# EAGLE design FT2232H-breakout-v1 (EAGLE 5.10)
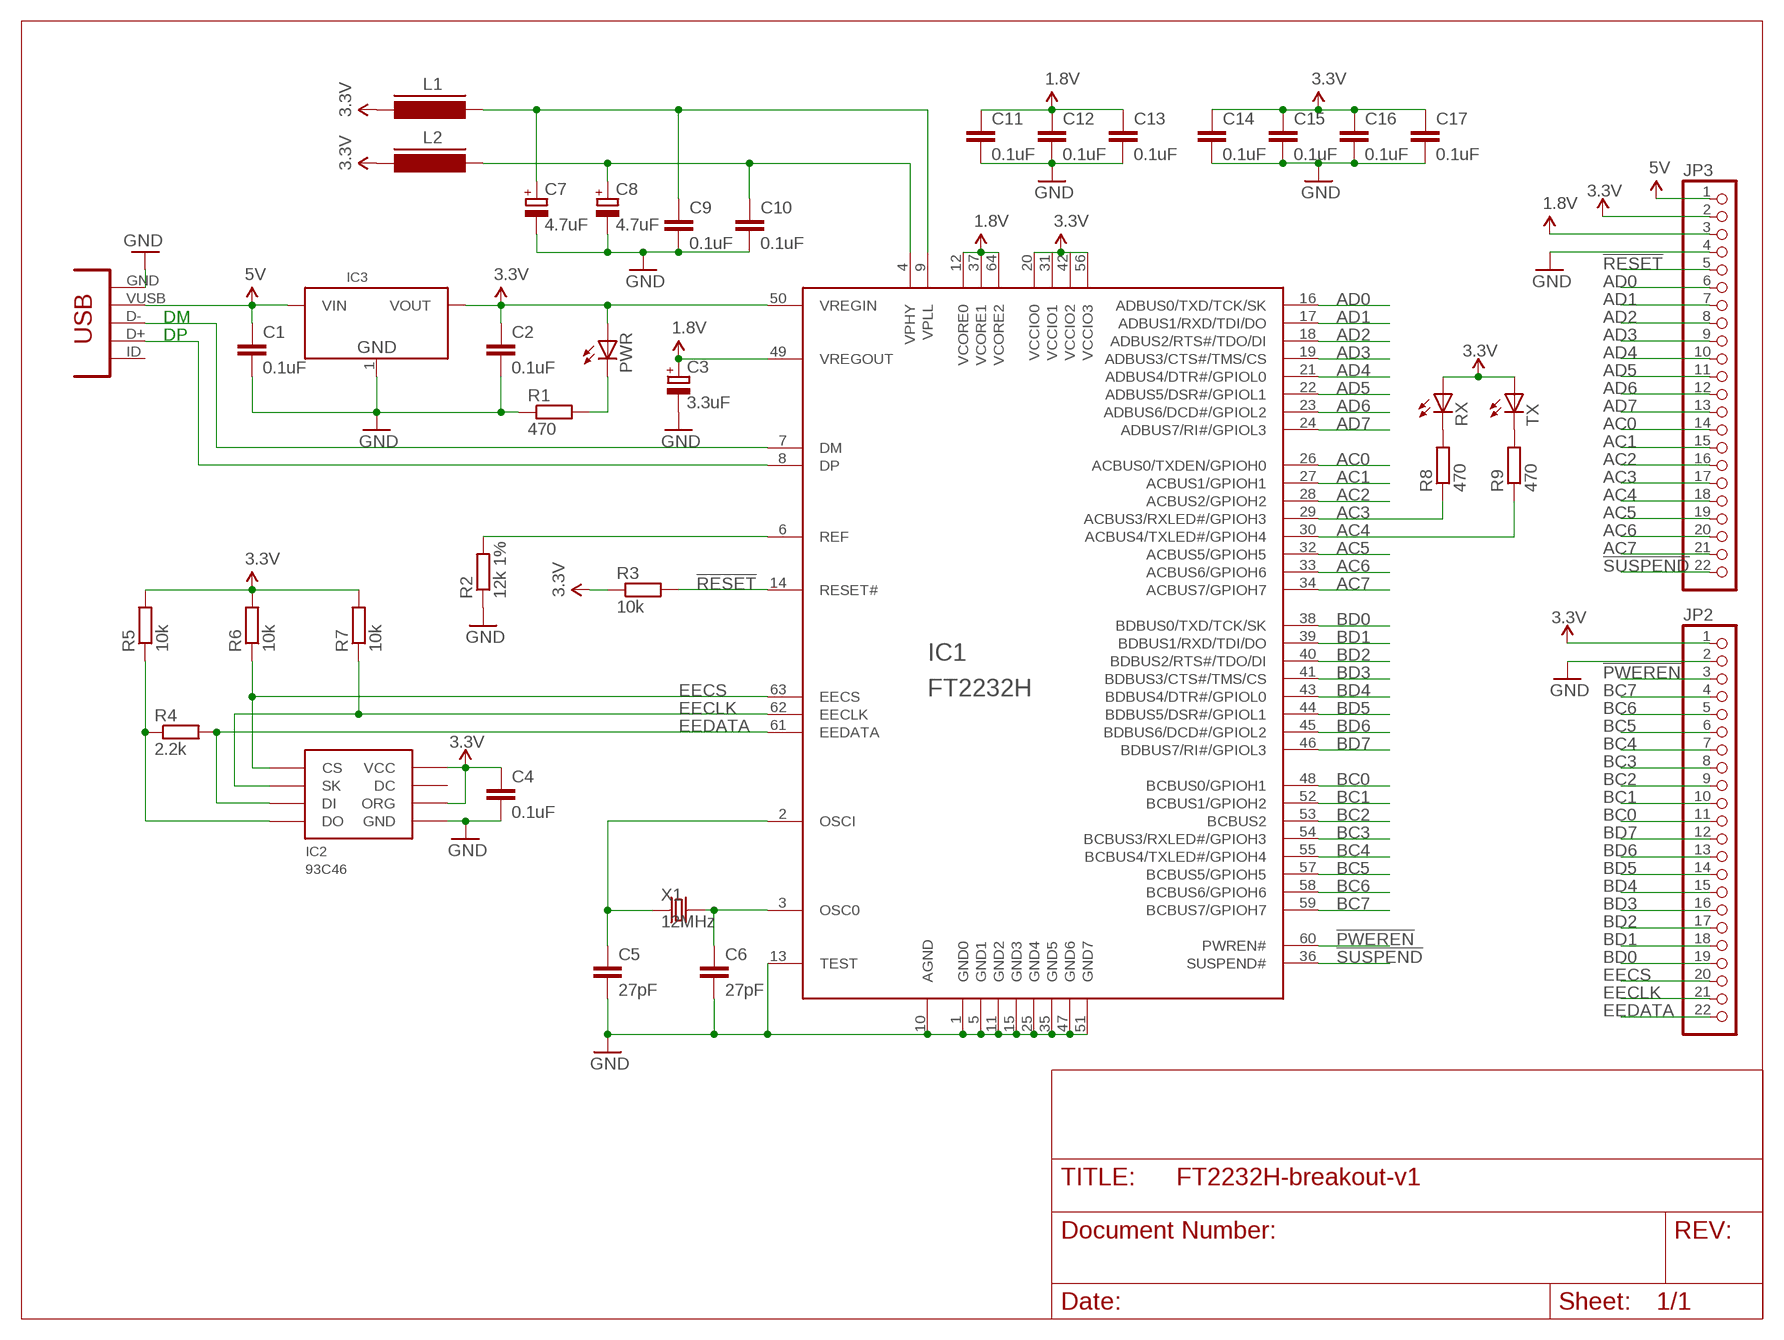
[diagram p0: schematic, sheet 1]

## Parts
C1  0.1uF  CAPC805  [C805]
C2  0.1uF  CAPC805  [C805]
C3  3.3uF  CAP_POLSMC_A  [SMC_A]
C4  0.1uF  CAPC805  [C805]
C5  27pF  CAPC805  [C805]
C6  27pF  CAPC805  [C805]
C7  4.7uF  CAP_POLSMC_A  [SMC_A]
C8  4.7uF  CAP_POLSMC_A  [SMC_A]
C9  0.1uF  CAPC805  [C805]
C10  0.1uF  CAPC805  [C805]
C11  0.1uF  CAPC805  [C805]
C12  0.1uF  CAPC805  [C805]
C13  0.1uF  CAPC805  [C805]
C14  0.1uF  CAPC805  [C805]
C15  0.1uF  CAPC805  [C805]
C16  0.1uF  CAPC805  [C805]
C17  0.1uF  CAPC805  [C805]
CONN1  CONN_USB  [CONN_USB_MINI-B]
IC1  FT2232H  [LQFP64]
IC2  93C46  [SOIC8]
IC3  LD1117-3.3SOT223  [SOT223]
JP2  PINHD-1X22  [1X22]
JP3  PINHD-1X22  [1X22]
L1  FERRITE_BEAD805  [FB805]
L2  FERRITE_BEAD805  [FB805]
PWR  LED805  [LED-805]
R1  470  RESISTORR805R805  [R805]
R2  12k 1%  RESISTORR805R805  [R805]
R3  10k  RESISTORR805R805  [R805]
R4  2.2k  RESISTORR805R805  [R805]
R5  10k  RESISTORR805R805  [R805]
R6  10k  RESISTORR805R805  [R805]
R7  10k  RESISTORR805R805  [R805]
R8  470  RESISTORR805R805  [R805]
R9  470  RESISTORR805R805  [R805]
RX  LED805  [LED-805]
TX  LED805  [LED-805]
X1  12MHz  CRYSTAL_212M_  [4X6]

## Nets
1.8V: C3.+ C11.1 C12.1 C13.1 IC1.12(VCORE0) IC1.37(VCORE1) IC1.49(VREGOUT) IC1.64(VCORE2) JP3.3
3.3V: C2.1 C4.1 C14.1 C15.1 C16.1 C17.1 IC1.20(VCCIO0) IC1.31(VCCIO1) IC1.42(VCCIO2) IC1.50(VREGIN) IC1.56(VCCIO3) IC2.6(ORG) IC2.8(VCC) IC3.2(VOUT) JP2.1 JP3.2 L1.2 L2.2 PWR.A R3.1 R5.2 R6.2 R7.2 RX.A TX.A
5V: C1.1 CONN1.VUSB IC3.3(VIN) JP3.1
!PWEREN: IC1.60(PWREN#) JP2.3
!RESET: IC1.14(RESET#) JP3.5 R3.2
!SUSPEND: IC1.36(SUSPEND#) JP3.22
AC0: IC1.26(ACBUS0/TXDEN/GPIOH0) JP3.14
AC1: IC1.27(ACBUS1/GPIOH1) JP3.15
AC2: IC1.28(ACBUS2/GPIOH2) JP3.16
AC3: IC1.29(ACBUS3/RXLED#/GPIOH3) JP3.17 R8.1
AC4: IC1.30(ACBUS4/TXLED#/GPIOH4) JP3.18 R9.1
AC5: IC1.32(ACBUS5/GPIOH5) JP3.19
AC6: IC1.33(ACBUS6/GPIOH6) JP3.20
AC7: IC1.34(ACBUS7/GPIOH7) JP3.21
AD0: IC1.16(ADBUS0/TXD/TCK/SK) JP3.6
AD1: IC1.17(ADBUS1/RXD/TDI/DO) JP3.7
AD2: IC1.18(ADBUS2/RTS#/TDO/DI) JP3.8
AD3: IC1.19(ADBUS3/CTS#/TMS/CS) JP3.9
AD4: IC1.21(ADBUS4/DTR#/GPIOL0) JP3.10
AD5: IC1.22(ADBUS5/DSR#/GPIOL1) JP3.11
AD6: IC1.23(ADBUS6/DCD#/GPIOL2) JP3.12
AD7: IC1.24(ADBUS7/RI#/GPIOL3) JP3.13
BC0: IC1.48(BCBUS0/GPIOH1) JP2.11
BC1: IC1.52(BCBUS1/GPIOH2) JP2.10
BC2: IC1.53(BCBUS2) JP2.9
BC3: IC1.54(BCBUS3/RXLED#/GPIOH3) JP2.8
BC4: IC1.55(BCBUS4/TXLED#/GPIOH4) JP2.7
BC5: IC1.57(BCBUS5/GPIOH5) JP2.6
BC6: IC1.58(BCBUS6/GPIOH6) JP2.5
BC7: IC1.59(BCBUS7/GPIOH7) JP2.4
BD0: IC1.38(BDBUS0/TXD/TCK/SK) JP2.19
BD1: IC1.39(BDBUS1/RXD/TDI/DO) JP2.18
BD2: IC1.40(BDBUS2/RTS#/TDO/DI) JP2.17
BD3: IC1.41(BDBUS3/CTS#/TMS/CS) JP2.16
BD4: IC1.43(BDBUS4/DTR#/GPIOL0) JP2.15
BD5: IC1.44(BDBUS5/DSR#/GPIOL1) JP2.14
BD6: IC1.45(BDBUS6/DCD#/GPIOL2) JP2.13
BD7: IC1.46(BDBUS7/RI#/GPIOL3) JP2.12
DM: CONN1.D- IC1.7(DM)
DP: CONN1.D+ IC1.8(DP)
EECLK: IC1.62(EECLK) IC2.2(SK) JP2.21 R7.1
EECS: IC1.63(EECS) IC2.1(CS) JP2.20 R6.1
EEDATA: IC1.61(EEDATA) IC2.3(DI) JP2.22 R4.2
GND: C1.2 C2.2 C3.- C4.2 C5.2 C6.2 C7.- C8.- C9.2 C10.2 C11.2 C12.2 C13.2 C14.2 C15.2 C16.2 C17.2 CONN1.GND IC1.1(GND0) IC1.5(GND1) IC1.10(AGND) IC1.11(GND2) IC1.13(TEST) IC1.15(GND3) IC1.25(GND4) IC1.35(GND5) IC1.47(GND6) IC1.51(GND7) IC2.5(GND) IC3.1(GND) JP2.2 JP3.4 R1.1 R2.1
N$1: PWR.C R1.2
N$2: R8.2 RX.C
N$3: R9.2 TX.C
N$4: IC1.6(REF) R2.2
N$9: C5.1 IC1.2(OSCI) X1.1(X1)
N$10: C6.1 IC1.3(OSC0) X1.2(X2)
N$45: IC2.4(DO) R4.1 R5.1
N$48: C8.+ C10.1 IC1.4(VPHY) L2.1
N$49: C7.+ C9.1 IC1.9(VPLL) L1.1
Unconnected: CONN1.BODY@1(BODY) CONN1.BODY@2(BODY) CONN1.BODY@3(BODY) CONN1.BODY@4(BODY) CONN1.ID(USBID) IC2.7(DC)

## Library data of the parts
C1 C2 C4-C6 C9-C17 = dp_devices:CAP
C3 C7 C8 = dp_devices:CAP_POL
CONN1 = dp_devices:CONN_USB: USB connector
IC1 = DP-EagleLibrary:FT2232H: DUAL HIGH SPEED USB TO MULTIPURPOSE UART/FIFO IC
IC2 = dp_devices:93C46; 93C46: 93C46
IC3 = dp_devices:LD1117-3.3
JP2 JP3 = pinhead - Copy:PINHD-1X22: PIN HEADER
L1 L2 = dp_devices:FERRITE_BEAD
PWR RX TX = dp_devices:LED
R1-R9 = dp_devices:RESISTOR
X1 = dp_devices:CRYSTAL_2

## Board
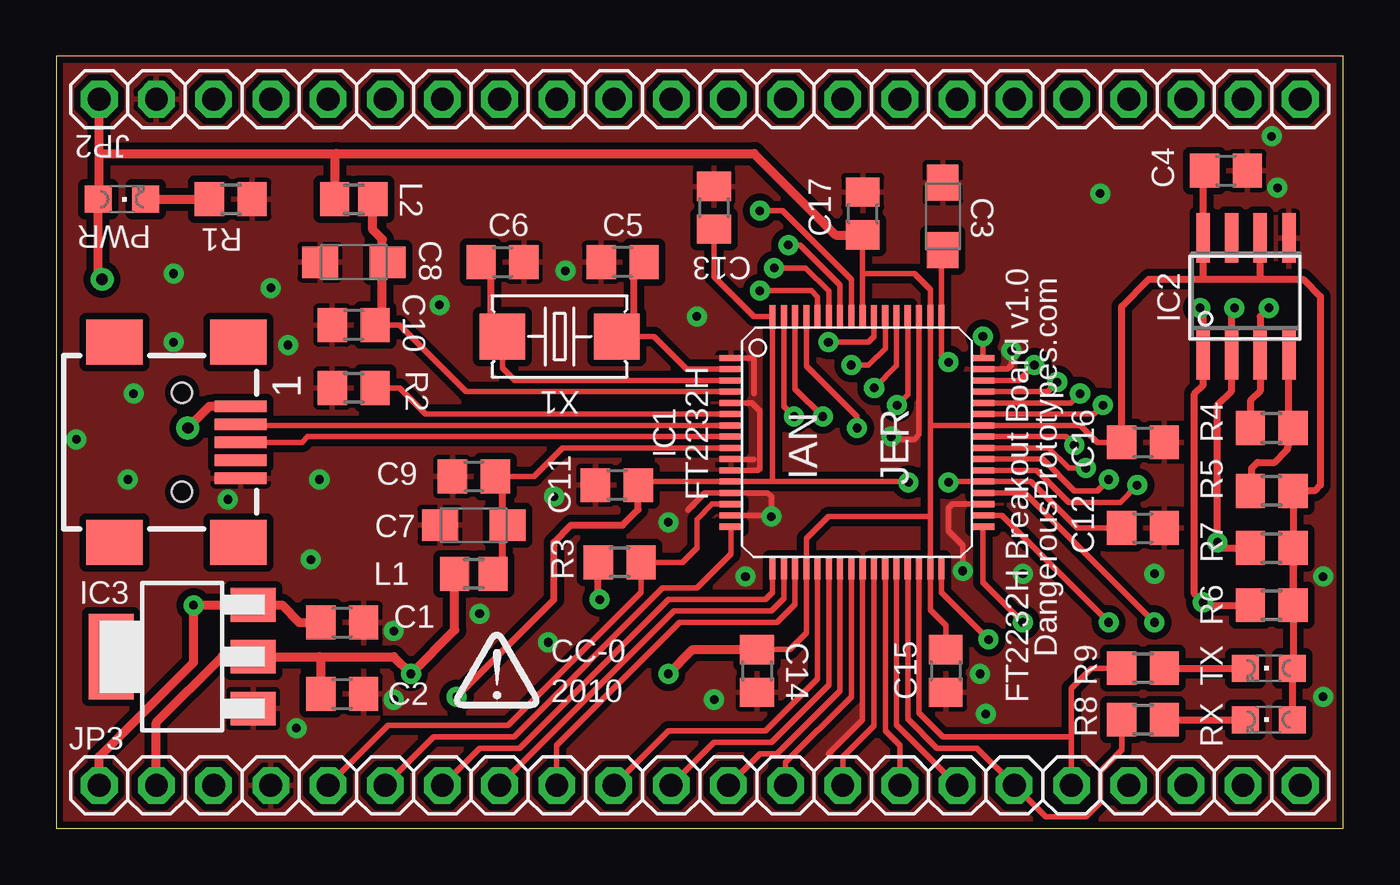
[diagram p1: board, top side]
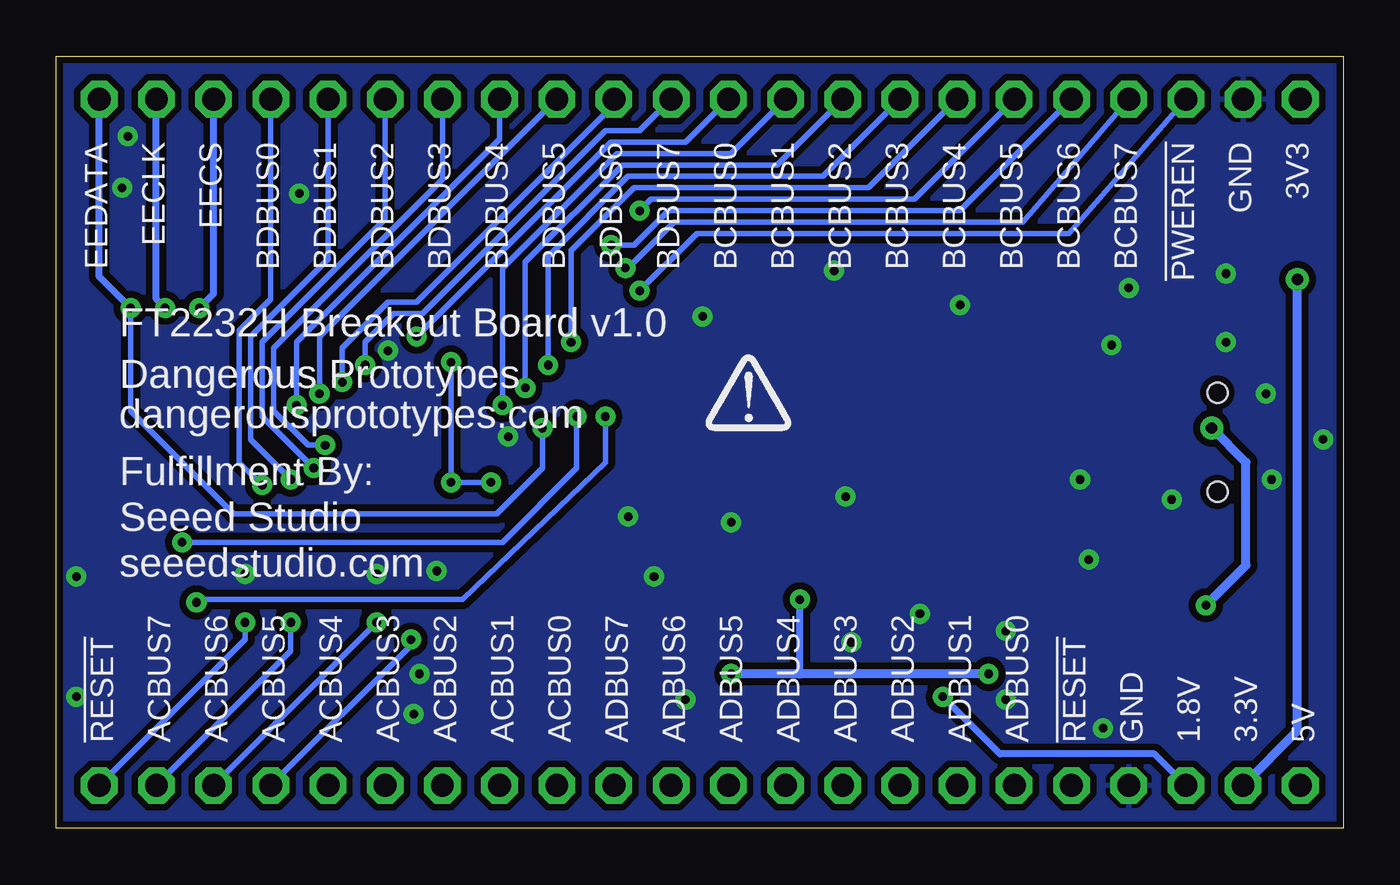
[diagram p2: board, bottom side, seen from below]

Size 57.15 x 34.29 mm. Coordinates in mm from the lower left corner, seen from the top.
Outline: 0,0 57.15,0 57.15,34.29 0,34.29 0,0
Copper layers (1*16): Top 0.035mm / dielectric 1.5mm / Bottom 0.035mm
Design rules "SparkFun *": minimum track width 8mil, minimum drill 15mil, track to track 8mil, track to pad 8mil, pad to pad 8mil, via to via 8mil, smd to smd 8mil, copper to edge 10mil, drill to drill 8mil, minimum pad ring 12mil, minimum via ring 10mil, stop-mask expansion 4mil, vias tented up to drill 25mil, thermal gap 8mil

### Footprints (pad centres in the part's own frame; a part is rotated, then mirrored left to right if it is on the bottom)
C805 = smd 1.3 x 1.5: 1 -0.95,0; 2 0.95,0
SMC_A = smd 1.6 x 1.4: + -1.5,0; - 1.5,0
CONN_USB_MINI-B = smd 2 x 2.5: BODY@1 -4.45,2.5; BODY@2 4.45,2.5; BODY@3 4.45,-3; BODY@4 -4.45,-3 | smd 0.5 x 2.3: D+ 0,2.6; D- -0.8,2.6; GND 1.6,2.6; ID 0.8,2.6; VUSB -1.6,2.6 | hole 0.9: -2.2,0; 2.2,0
LQFP64 = smd 1 x 0.27: 1 -5.6,3.75; 2 -5.6,3.25; 3 -5.6,2.75; 4 -5.6,2.25; 5 -5.6,1.75; 6 -5.6,1.25; 7 -5.6,0.75; 8 -5.6,0.25; 9 -5.6,-0.25; 10 -5.6,-0.75; 11 -5.6,-1.25; 12 -5.6,-1.75; 13 -5.6,-2.25; 14 -5.6,-2.75; 15 -5.6,-3.25; 16 -5.6,-3.75; 33 5.6,-3.75; 34 5.6,-3.25; 35 5.6,-2.75; 36 5.6,-2.25; 37 5.6,-1.75; 38 5.6,-1.25; 39 5.6,-0.75; 40 5.6,-0.25; 41 5.6,0.25; 42 5.6,0.75; 43 5.6,1.25; 44 5.6,1.75; 45 5.6,2.25; 46 5.6,2.75; 47 5.6,3.25; 48 5.6,3.75 | smd 0.27 x 1: 17 -3.75,-5.6; 18 -3.25,-5.6; 19 -2.75,-5.6; 20 -2.25,-5.6; 21 -1.75,-5.6; 22 -1.25,-5.6; 23 -0.75,-5.6; 24 -0.25,-5.6; 25 0.25,-5.6; 26 0.75,-5.6; 27 1.25,-5.6; 28 1.75,-5.6; 29 2.25,-5.6; 30 2.75,-5.6; 31 3.25,-5.6; 32 3.75,-5.6; 49 3.75,5.6; 50 3.25,5.6; 51 2.75,5.6; 52 2.25,5.6; 53 1.75,5.6; 54 1.25,5.6; 55 0.75,5.6; 56 0.25,5.6; 57 -0.25,5.6; 58 -0.75,5.6; 59 -1.25,5.6; 60 -1.75,5.6; 61 -2.25,5.6; 62 -2.75,5.6; 63 -3.25,5.6; 64 -3.75,5.6
SOIC8 = smd 0.6 x 2.2: 1 -1.905,-2.6; 2 -0.635,-2.6; 3 0.635,-2.6; 4 1.905,-2.6; 5 1.905,2.6; 6 0.635,2.6; 7 -0.635,2.6; 8 -1.905,2.6
SOT223 = smd 1.5 x 2: 1 -2.3,-3.15; 2 0,-3.15; 3 2.3,-3.15 | smd 3.8 x 2: 4 0,3.15
1X22 = drill 1.016 octagon: 1 -26.67,0; 2 -24.13,0; 3 -21.59,0; 4 -19.05,0; 5 -16.51,0; 6 -13.97,0; 7 -11.43,0; 8 -8.89,0; 9 -6.35,0; 10 -3.81,0; 11 -1.27,0; 12 1.27,0; 13 3.81,0; 14 6.35,0; 15 8.89,0; 16 11.43,0; 17 13.97,0; 18 16.51,0; 19 19.05,0; 20 21.59,0; 21 24.13,0; 22 26.67,0
FB805 = smd 1.3 x 1.5: 1 -0.85,0; 2 0.85,0
LED-805 = smd 1.2 x 1.2: A 0,-1.05; C 0,1.05
R805 = smd 1.3 x 1.5: 1 -0.95,0; 2 0.95,0
4X6 = smd 2.032 x 2.032: 1 -2.54,0; 2 2.54,0

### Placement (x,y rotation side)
C1  12.7,9.14 0 top
C2  12.7,5.97 0 top
C3  39.37,27.18 90 top
C4  51.94,29.21 0 top
C5  25.15,25.15 180 top
C6  19.81,25.15 0 top
C7  18.54,13.46 180 top
C8  13.21,25.15 180 top
C9  18.54,15.62 180 top
C10  13.21,22.35 180 top
C11  24.89,15.24 180 top
C12  48.26,13.34 0 top
C13  29.21,27.56 90 top
C14  31.11,6.99 270 top
C15  39.5,6.99 270 top
C16  48.26,17.14 0 top
C17  35.81,27.3 90 top
CONN1  5.59,17.14 270 top
IC1  35.56,17.14 0 top
IC2  52.83,23.62 0 top
IC3  5.59,7.62 90 top
JP2  28.57,32.38 0 top
JP3  28.57,1.91 0 top
L1  18.54,11.3 180 top
L2  13.21,27.94 180 top
PWR  2.92,27.94 270 top
R1  7.75,27.94 180 top
R2  13.21,19.56 0 top
R3  25.02,11.81 0 top
R4  53.98,17.78 180 top
R5  53.98,14.99 0 top
R6  53.98,9.91 0 top
R7  53.98,12.45 0 top
R8  48.26,4.83 0 top
R9  48.26,7.11 0 top
RX  53.85,4.83 90 top
TX  53.85,7.11 90 top
U$7  [DP_LOGO]  19.56,5.97 0 top
U$8  [DP_LOGO]  26.42,18.29 0 bottom
X1  22.35,21.84 180 top

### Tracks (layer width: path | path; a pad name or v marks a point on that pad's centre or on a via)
1.8V  (via drill 0.38)
  Top 0.254: C13.1 29.21,24.51 30.99,22.73 31.8,22.73 | 31.75,15.39 IC1.12 26.25,15.39 C11.1 | 31.75,15.39 37.56,15.39 v37.85,15.37 | v39.62,15.37 39.65,15.39 IC1.37 43.28,15.39 45.34,13.34 C12.1 | v39.62,20.7 39.31,21.02 IC1.49 39.31,25.62 C3.+ | 31.8,22.73 31.8,15.44 31.75,15.39 | 31.8,22.73 IC1.64
  Top 0.305: C11.1 25.84,14.16 25.15,13.46 22.86,13.46 22.1,12.7 22.1,10.16 v17.78,5.84
  Bottom 0.254: v37.85,15.37 v39.62,15.37 v39.62,20.7
  Bottom 0.305: v17.78,5.84 15.24,3.3 8.38,3.3 JP3.3
3.3V  (via drill 0.38, 0.51)
  Top 0.254: C16.1 46.23,17.14 45.48,17.89 IC1.42 38.82,17.89 38.81,17.91 | 38.81,13.84 IC1.31 38.81,9.7 39.5,9.02 C15.1 | 38.81,17.91 38.81,13.84 | 38.81,17.91 IC1.50 38.81,23.93 38.1,24.64 35.81,24.64 | 38.81,13.84 34.29,13.84 33.31,12.86 IC1.20 33.31,8.67 32.57,7.93 C14.1 | 35.81,24.64 IC1.56 | 35.81,24.64 C17.1
  Top 0.305: C4.1 50.93,29.14 IC2.8 50.93,24.51 51.05,24.38 | C16.1 47.31,23.18 48.51,24.38 51.05,24.38 | R6.2 R5.2 55.88,14.99 56.13,15.24 56.13,23.62 55.37,24.38 53.59,24.38 | R6.2 R7.2 | 51.05,24.38 53.59,24.38 | IC2.6 53.47,24.51 53.59,24.38 | R6.2 54.92,7.14 TX.A RX.A | R3.1 24.07,10.22 v24.13,10.16
  Top 0.406: 11.68,7.62 IC3.2 7.37,7.62 4.45,4.7 JP3.2 | 11.68,7.62 14.99,7.62 v15.75,6.86 17.69,8.8 L1.2 | C2.1 11.75,7.55 11.68,7.62 | C17.1 34.6,26.36 30.99,29.97 12.45,29.97 | 1.91,29.97 1.91,28.23 PWR.A 1.87,24.55 v2.03,24.38 | 1.91,29.97 JP2.1 | 1.91,29.97 12.45,29.97 | L2.2 12.36,29.88 12.45,29.97 | C14.1 28.25,7.93 v27.18,6.86
  Bottom 0.305: 24.13,6.86 v24.13,10.16
  Bottom 0.406: v15.75,6.86 24.13,6.86 v27.18,6.86 | v2.03,24.38 2.03,4.32 JP3.2
5V  (via drill 0.38, 0.51)
  Top 0.305: v6.1,9.91 v6.11,9.92
  Top 0.406: C1.1 10.79,9.14 10.02,9.92 IC3.3 v6.11,9.92 | CONN1.VUSB 6.81,18.75 v5.84,17.78 | v6.1,9.91 6.1,7.37 1.91,3.17 JP3.1
  Bottom 0.406: v5.84,17.78 4.32,16.26 4.32,11.68 v6.1,9.91
!PWEREN  (via drill 0.38)
  Top 0.254: IC1.60 33.81,23.59 33.53,23.88 v31.24,23.88
  Bottom 0.254: v31.24,23.88 28.7,26.42 12.19,26.42 JP2.3
!RESET
  Top 0.254: JP3.5 14.73,4.57 20.07,4.57 25.97,10.47 R3.2 27.81,11.81 28.45,12.45 28.45,13.72 29.13,14.39 IC1.14
!SUSPEND  (via drill 0.38)
  Top 0.254: IC1.36 43.02,14.89 v48.77,9.14
  Bottom 0.254: v48.77,9.14 48.77,8.38 JP3.22
AC0
  Top 0.254: IC1.26 36.31,4.56 34.92,3.17 JP3.14
AC1
  Top 0.254: IC1.27 36.81,4.34 37.47,3.68 JP3.15
AC2
  Top 0.254: IC1.28 37.31,4.6 JP3.16
AC3
  Top 0.254: IC1.29 37.81,4.86 39.12,3.56 40.89,3.56 JP3.17 43.94,0.51 45.72,0.51 46.35,1.14 46.35,2.54 47.31,3.5 R8.1
AC4
  Top 0.254: R9.1 45.97,7.11 45.09,6.22 45.09,4.06 | 45.09,4.06 JP3.18 | 45.09,4.06 39.37,4.06 38.31,5.12 IC1.30
AC5  (via drill 0.38)
  Top 0.254: IC1.32 39.31,10.47 v41.4,8.38
  Bottom 0.254: v41.4,8.38 41.4,8.13 JP3.19
AC6  (via drill 0.38)
  Top 0.254: IC1.33 41.16,10.91 v42.93,9.14
  Bottom 0.254: JP3.20 v42.93,9.14
AC7  (via drill 0.38)
  Top 0.254: IC1.34 41.98,13.89 v46.74,9.14
  Bottom 0.254: v46.74,9.14 46.74,7.87 JP3.21
AD0
  Top 0.254: IC1.16 29.96,12.18 28.45,10.67 26.92,10.67 20.32,4.06 16.76,4.06 JP3.6
AD1
  Top 0.254: IC1.17 31.81,10.47 31.5,10.16 27.18,10.16 20.57,3.56 18.8,3.56 JP3.7
AD2
  Top 0.254: IC1.18 32.31,10.21 31.75,9.65 27.43,9.65 JP3.8
AD3
  Top 0.254: IC1.19 32.81,9.95 32,9.14 27.69,9.14 22.23,3.68 JP3.9
AD4
  Top 0.254: IC1.21 33.81,6.63 31.5,4.32 27.18,4.32 JP3.10
AD5
  Top 0.254: IC1.22 34.31,6.37 31.75,3.81 29.21,3.81 JP3.11
AD6
  Top 0.254: IC1.23 34.81,6.11 32,3.3 31.24,3.3 JP3.12
AD7
  Top 0.254: IC1.24 35.31,5.85 32.38,2.92 JP3.13
BC0  (via drill 0.38)
  Top 0.254: IC1.48 v41.16,21.83 v41.15,21.84
  Bottom 0.254: v41.15,21.84 32.51,30.48 29.21,30.48 JP2.11
BC1  (via drill 0.38)
  Top 0.254: IC1.52 37.81,19.27 v37.34,18.8
  Bottom 0.254: v37.34,18.8 37.34,24.89 32.26,29.97 27.18,29.97 JP2.10
BC2  (via drill 0.38)
  Top 0.254: IC1.53 37.31,20.55 v36.32,19.56
  Bottom 0.254: v36.32,19.56 36.32,25.15 32,29.46 25.15,29.46 JP2.9
BC3  (via drill 0.38)
  Top 0.254: IC1.54 36.81,21.32 36.07,20.57 v35.31,20.57
  Bottom 0.254: v35.31,20.57 35.31,25.4 31.75,28.96 23.11,28.96 JP2.8
BC4  (via drill 0.38)
  Top 0.254: IC1.55 36.31,21.83 36.07,21.59 v34.29,21.59
  Bottom 0.254: v34.29,21.59 34.29,25.65 31.5,28.45 21.08,28.45 JP2.7
BC5  (via drill 0.38)
  Top 0.254: IC1.57 35.31,24.38 32.26,27.43 v31.24,27.43
  Bottom 0.254: JP2.6 19.05,27.94 30.73,27.94 v31.24,27.43
BC6  (via drill 0.38)
  Top 0.254: IC1.58 34.81,24.12 33.02,25.91 v32.51,25.91
  Bottom 0.254: v32.51,25.91 31.5,25.91 29.97,27.43 17.02,27.43 JP2.5
BC7  (via drill 0.38)
  Top 0.254: IC1.59 34.31,23.86 33.27,24.89 v31.88,24.89
  Bottom 0.254: v31.88,24.89 31.75,24.89 29.72,26.92 14.22,26.92 JP2.4
BD0  (via drill 0.38)
  Top 0.254: IC1.38 43.54,15.89 44.96,14.48 47.24,14.48 v48.01,15.24
  Bottom 0.254: v48.01,15.24 49.02,16.26 49.02,22.1 47.62,23.5 JP2.19
BD1  (via drill 0.38)
  Top 0.254: IC1.39 43.8,16.39 45.21,14.99 46.23,14.99 v46.74,15.49
  Bottom 0.254: v46.74,15.49 48.51,17.27 48.51,21.84 45.09,25.27 JP2.18
BD2  (via drill 0.38)
  Top 0.254: IC1.40 44.06,16.89 44.96,16 v45.72,16
  Bottom 0.254: v45.72,16 48.01,18.29 48.01,21.59 42.55,27.05 JP2.17
BD3  (via drill 0.38)
  Top 0.254: IC1.41 44.84,17.39 v45.21,17.02
  Bottom 0.254: v45.21,17.02 45.97,17.02 47.5,18.54 47.5,21.34 40.01,28.83 JP2.16
BD4  (via drill 0.38)
  Top 0.254: IC1.43 46.08,18.39 v46.48,18.8
  Bottom 0.254: v46.48,18.8 46.48,21.59 37.47,30.61 JP2.15
BD5  (via drill 0.38)
  Top 0.254: IC1.44 45.06,18.89 v45.47,19.3
  Bottom 0.254: v45.47,19.3 45.47,21.84 JP2.14
BD6  (via drill 0.38)
  Top 0.254: IC1.45 44.03,19.39 v44.45,19.81
  Bottom 0.254: v44.45,19.81 44.45,21.34 42.42,23.37 41.15,23.37 32.51,32 32.51,32.38 JP2.13
BD7  (via drill 0.38)
  Top 0.254: IC1.46 42.76,19.89 v43.43,20.57
  Bottom 0.254: v43.43,20.57 43.43,21.59 42.16,22.86 40.89,22.86 32.77,30.99 31.24,30.99 JP2.12
DM
  Top 0.254: IC1.7 8.19,17.89 CONN1.D-
DP
  Top 0.254: IC1.8 11.17,17.39 10.92,17.14 CONN1.D+
EECLK  (via drill 0.38)
  Top 0.254: IC1.62 32.81,19.51 v34.04,18.29
  Top 0.305: v52.32,23.11 52.2,22.99 IC2.2 52.2,19.43 51.56,18.8 v51.56,12.7 51.82,12.45 R7.1
  Bottom 0.254: v34.04,18.29 34.04,16 37.34,12.7 v51.56,12.7
  Bottom 0.305: JP2.21 52.7,23.5 v52.32,23.11
EECS  (via drill 0.38)
  Top 0.254: IC1.63 32.31,18.74 v32.77,18.29
  Top 0.305: v50.8,23.11 50.93,22.99 IC2.1 50.93,19.68 50.55,19.3 50.55,10.41 v50.93,10.03 51.05,9.91 R6.1
  Bottom 0.254: v32.77,18.29 32.77,16.26 39.12,10.16 50.8,10.16 v50.93,10.03
  Bottom 0.305: JP2.20 50.16,23.75 v50.8,23.11
EEDATA  (via drill 0.38)
  Top 0.254: IC1.61 33.31,20.54 35.56,18.29 v35.56,17.78
  Top 0.305: R4.2 53.02,18.99 53.47,19.43 IC2.3 53.47,22.73 v53.85,23.11
  Bottom 0.254: v35.56,17.78 35.56,16 37.59,13.97 49.28,13.97 53.85,18.54 v53.85,23.11
  Bottom 0.305: JP2.22 55.24,24.51 v53.85,23.11
GND  (via drill 0.38)
  Top 0.254: IC1.15 31.75,13.89 v31.75,13.84 31.75,14.73 31.59,14.89 IC1.13 | IC1.11 31.14,15.89 31.24,16 31.24,18.54 30.89,18.89 IC1.5 | IC1.1 30.92,20.89 30.99,20.83 30.99,19.3 | IC1.47 42.24,20.39 42.42,20.57 v42.42,21.21 | IC1.51 38.31,17.48 38.1,17.27 37.21,17.27 v37.08,17.4 | IC1.35 39.8,14.39 39.62,14.22 39.62,13.21 40.26,12.57 v40.26,11.43 | IC1.25 35.81,4.82 34.29,3.3 | 29.97,16.38 30.99,16.38 | 30.01,14.9 28.82,14.9 28.05,14.13
  other vias: 14.99,8.76 14.99,5.71 10.67,4.45 11.68,15.49 7.62,14.61 29.21,5.71 18.8,9.53 28.45,22.73 22.61,24.77 21.84,8.26 17.02,23.24 42.93,11.3 48.77,11.3 5.21,21.59 9.53,24 22.1,14.73 27.18,13.59 10.29,21.46 3.43,19.3 3.17,15.49 0.89,17.27 11.3,11.94 5.21,24.64 56.26,11.18 56.26,5.84 41.02,6.86 41.27,5.08 30.61,11.18 46.35,28.19 53.98,30.73 54.23,28.45
  pour Bottom (isolate 0.305): 0,0 57.15,0 57.15,34.29 0,34.29
  pour Top (isolate 0.305): 0,0 57.15,0 57.15,34.29 0,34.29
N$1
  Top 0.406: PWR.C R1.2
N$2
  Top 0.305: R8.2 RX.C
N$3
  Top 0.305: R9.2 TX.C
N$4
  Top 0.254: IC1.6 16.4,18.39 15.24,19.56 R2.2
N$9
  Top 0.254: IC1.2 27.99,20.39 26.54,21.84 25.4,21.84 X1.1
  Top 0.305: C5.1 25.91,25.15 25.65,24.89 25.65,22.1 25.4,21.84
N$10
  Top 0.254: IC1.3 20.36,19.89 19.81,20.45 X1.2
  Top 0.305: C6.1 18.86,25.08 19.05,24.89 19.3,24.89 19.3,22.35 X1.2
N$45
  Top 0.305: IC2.4 54.74,17.34 R4.1 54.67,16.82 54.1,16.26 53.34,16.26 53.09,16 53.09,15.24 R5.1
N$48
  Top 0.254: IC1.4 18.2,19.39 15.24,22.35 C10.1
  Top 0.406: C10.1 14.16,22.03 14.48,22.35 14.48,24.49 | 14.48,24.79 C8.+ 14.48,24.49 | L2.1 14.06,26.58 14.48,26.16 14.48,24.79 | 14.48,24.49 14.48,24.79
N$49
  Top 0.254: IC1.9 22.48,16.89 21.21,15.62 C9.1 19.49,15.56 19.81,15.24
  Top 0.305: 19.81,15.24 19.81,13.69 C7.+ 20.04,13.44 19.81,13.21 19.81,11.72 L1.1

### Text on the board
tNames: IAN | JER | DangerousPrototypes.com | CC-0 | 2010 | FT2232H Breakout Board v1.0
bNames: 3V3 | GND | !PWEREN | BCBUS7 | BCBUS6 | BCBUS5 | BCBUS4 | BCBUS3 | BCBUS2 | BCBUS1 | BCBUS0 | BDBUS7 | BDBUS6 | BDBUS5 | BDBUS4 | BDBUS3 | BDBUS2 | BDBUS1 | BDBUS0 | EECS | EECLK | EEDATA | FT2232H Breakout Board v1.0 | Dangerous Prototypes | dangerousprototypes.com | Fulfillment By: | Seeed Studio | seeedstudio.com | 5V | 3.3V | 1.8V | GND | !RESET | ADBUS0 | ADBUS1 | ADBUS2 | ADBUS3 | ADBUS4 | ADBUS5 | ADBUS6 | ADBUS7 | ACBUS0 | ACBUS1 | ACBUS2 | ACBUS3 | ACBUS4 | ACBUS5 | ACBUS6 | ACBUS7 | !RESET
